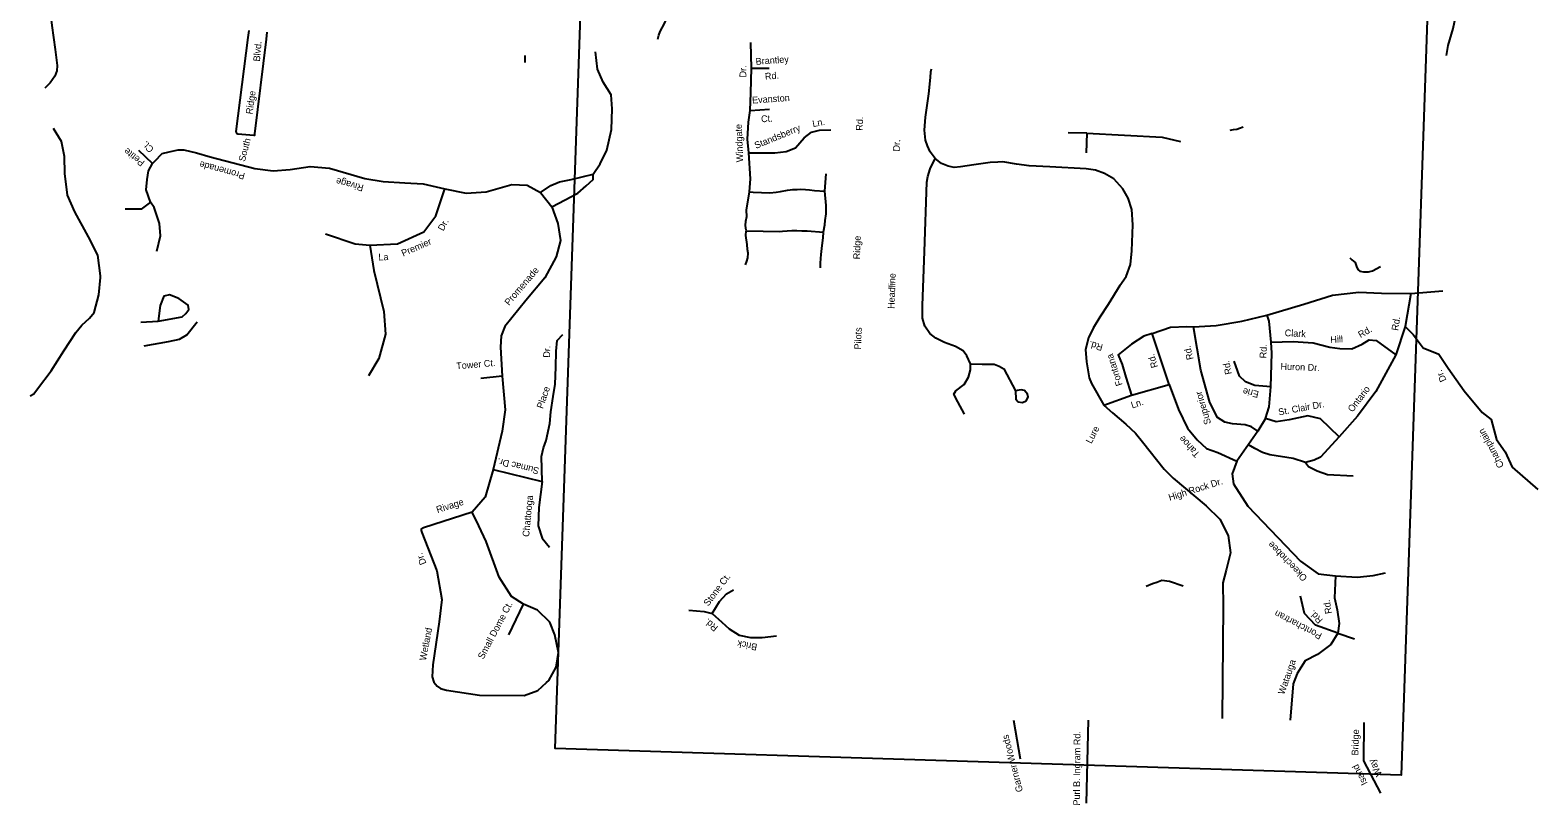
# Model space of a CAD drawing. Extents: x 2308163 to 2335412, y -96774 to 127732.
# Drawn here: x 2308692 to 2323317, y -96363 to -88852 of the extents above; entities that cross this region are included whole.
import ezdxf

# ---------------------------------------------------------------- set-up
doc = ezdxf.new("R2010")
doc.units = 0
for name, color, linetype in [('Old_Level_10', 7, 'Continuous'), ('Old_Level_35', 7, 'Continuous'), ('Old_Level_63', 7, 'Continuous')]:
    doc.layers.add(name, color=color, linetype=linetype)

msp = doc.modelspace()

# ---------------------------------------------------------------- linework, layer by layer
at = {"layer": 'Old_Level_35'}
for p, q in [((2310807, -88923), (2310816, -88856)), ((2310989, -88873), (2310981, -88940)), ((2313495, -89165), (2313493, -89097)), ((2316402, -90412), (2316415, -90245))]:
    msp.add_line(p, q, dxfattribs=at)
for points in [[(2314782, -88941), (2314789, -88901), (2314802, -88866), (2314844, -88788), (2314897, -88666), (2314973, -88472), (2315044, -88272), (2315156, -88000)], [(2308871, -88558), (2308875, -88590), (2308902, -88806), (2308935, -89040), (2308954, -89195), (2308952, -89248), (2308933, -89297), (2308885, -89364), (2308835, -89414)], [(2322432, -89098), (2322447, -89000), (2322494, -88836), (2322521, -88712), (2322527, -88652)], [(2310981, -88940), (2310869, -89858), (2310869, -89867), (2310868, -89870), (2310867, -89872), (2310864, -89873), (2310861, -89874), (2310705, -89860), (2310699, -89857), (2310696, -89852), (2310694, -89846), (2310693, -89841), (2310692, -89834), (2310807, -88923)], [(2313751, -90565), (2314005, -90432), (2314085, -90363), (2314152, -90301), (2314154, -90249), (2314222, -90148), (2314285, -90015), (2314330, -89816), (2314337, -89616), (2314329, -89480), (2314249, -89355), (2314195, -89230), (2314177, -89063)], [(2315671, -90421), (2315680, -90293), (2315663, -90041), (2315651, -89908), (2315660, -89743), (2315677, -89631), (2315683, -89460), (2315688, -89221), (2315682, -88971)], [(2315688, -89221), (2315862, -89221)], [(2317470, -90097), (2317422, -90031), (2317395, -89973), (2317377, -89918), (2317367, -89823), (2317378, -89695), (2317410, -89470), (2317426, -89311), (2317430, -89257), (2317434, -89228)], [(2315677, -89631), (2315865, -89618)], [(2320333, -89822), (2320366, -89816), (2320397, -89811), (2320424, -89802), (2320458, -89789)], [(2309375, -91234), (2309347, -91035), (2309258, -90857), (2309124, -90615), (2309054, -90452), (2309028, -90242), (2309024, -90076), (2308996, -89933), (2308920, -89807)], [(2315663, -90041), (2315916, -90043), (2316027, -90028), (2316117, -89993), (2316201, -89896), (2316270, -89841), (2316350, -89821), (2316459, -89819)], [(2318942, -89852), (2318761, -89848)], [(2318942, -89852), (2318934, -90042)], [(2318942, -89852), (2319674, -89890), (2319851, -89933)], [(2309880, -90145), (2309747, -90018)], [(2309858, -90519), (2309819, -90399), (2309828, -90300), (2309840, -90215), (2309880, -90145), (2309900, -90122), (2309974, -90049), (2310041, -90033), (2310127, -90012), (2310184, -90014), (2310306, -90042), (2310438, -90079)], [(2310438, -90079), (2310872, -90194), (2311049, -90216), (2311215, -90202), (2311409, -90173), (2311597, -90191), (2311937, -90289), (2312116, -90319), (2312328, -90331), (2312505, -90341), (2312716, -90391), (2312920, -90434), (2313117, -90421), (2313364, -90350), (2313513, -90356), (2313641, -90427), (2313751, -90565), (2313812, -90728), (2313838, -90890), (2313793, -91050), (2313683, -91255), (2313499, -91473), (2313297, -91726), (2313262, -91816), (2313254, -91926), (2313272, -92206), (2313300, -92534), (2313270, -92741), (2313182, -93112), (2313106, -93381), (2312979, -93526), (2312509, -93676), (2312484, -93690), (2312484, -93702), (2312491, -93722), (2312636, -94093), (2312686, -94371), (2312658, -94590), (2312597, -95005), (2312593, -95123), (2312607, -95175), (2312641, -95212), (2312671, -95236), (2312730, -95250), (2313051, -95301), (2313485, -95304), (2313616, -95253), (2313702, -95177), (2313722, -95158), (2313794, -95027), (2313818, -94886), (2313781, -94716), (2313734, -94592), (2313612, -94474), (2313476, -94418), (2313360, -94343), (2313241, -94154), (2313115, -93811), (2313045, -93659), (2312979, -93526)], [(2317812, -92086), (2317778, -92008), (2317743, -91961), (2317667, -91919), (2317560, -91879), (2317476, -91838), (2317418, -91793), (2317369, -91723), (2317347, -91646), (2317348, -91522), (2317368, -90997), (2317391, -90327), (2317400, -90272), (2317421, -90196), (2317470, -90097)], [(2319262, -91329), (2319323, -91241), (2319365, -91124), (2319377, -90992), (2319388, -90741), (2319378, -90590), (2319344, -90481), (2319292, -90391), (2319203, -90295), (2319112, -90242), (2319025, -90211), (2318937, -90196), (2318584, -90176), (2318381, -90167), (2318261, -90150), (2318128, -90130), (2318080, -90131), (2318004, -90136), (2317845, -90157), (2317716, -90178), (2317654, -90184), (2317597, -90171), (2317533, -90146), (2317470, -90097)], [(2313641, -90427), (2313743, -90358), (2313828, -90322), (2313939, -90300), (2314154, -90249)], [(2309922, -90995), (2309956, -90845), (2309946, -90726), (2309894, -90573), (2309858, -90519), (2309770, -90587), (2309614, -90587)], [(2311557, -90828), (2311845, -90925), (2311987, -90938), (2312255, -90923), (2312511, -90806), (2312627, -90653), (2312716, -90391)], [(2315636, -90792), (2315632, -90747), (2315634, -90703), (2315643, -90658), (2315642, -90597), (2315671, -90421)], [(2315671, -90421), (2315704, -90422), (2315785, -90427), (2315867, -90429), (2315927, -90424), (2315972, -90417), (2316038, -90405), (2316091, -90398), (2316132, -90398), (2316165, -90394), (2316214, -90397), (2316251, -90400), (2316300, -90407), (2316402, -90412)], [(2316386, -90808), (2316402, -90739), (2316404, -90698), (2316415, -90633), (2316412, -90552), (2316402, -90412)], [(2315630, -91128), (2315644, -91091), (2315653, -91060), (2315658, -91013), (2315650, -90978), (2315647, -90929), (2315635, -90844), (2315639, -90798)], [(2315642, -90797), (2315965, -90803), (2315989, -90801), (2316082, -90794), (2316129, -90795), (2316178, -90798), (2316228, -90798), (2316386, -90810)], [(2316357, -91157), (2316359, -91111), (2316361, -91066), (2316364, -91028), (2316372, -90970), (2316385, -90862), (2316389, -90813)], [(2311987, -90938), (2312026, -91183), (2312122, -91580), (2312138, -91801), (2312075, -92035), (2311975, -92205)], [(2321494, -91061), (2321514, -91078), (2321544, -91106), (2321558, -91143), (2321570, -91171), (2321590, -91188), (2321627, -91196), (2321673, -91196), (2321713, -91184), (2321789, -91142)], [(2308692, -92397), (2308728, -92377), (2308764, -92329), (2308895, -92154), (2309018, -91960), (2309135, -91783), (2309193, -91713), (2309268, -91643), (2309312, -91589), (2309359, -91419), (2309374, -91251), (2309375, -91234)], [(2319262, -91329), (2319148, -91513), (2319069, -91634), (2319005, -91742), (2318958, -91836), (2318930, -91948), (2318938, -92068), (2318965, -92222), (2318987, -92279), (2319107, -92489), (2319190, -92563), (2319319, -92672), (2319413, -92760), (2319482, -92842), (2319691, -93107), (2319778, -93196), (2320100, -93463), (2320232, -93593), (2320312, -93751), (2320336, -93918), (2320295, -94087), (2320261, -94211), (2320263, -94437), (2320254, -95525)], [(2319575, -91793), (2319753, -91733), (2319913, -91724), (2319976, -91728), (2320195, -91716), (2320446, -91675), (2320687, -91616), (2321048, -91509), (2321326, -91420), (2321581, -91393), (2321799, -91401), (2322085, -91404)], [(2322085, -91404), (2322030, -91724), (2321939, -92001), (2321745, -92357), (2321569, -92594), (2321388, -92795), (2321208, -92991), (2321148, -93022), (2321063, -93044), (2320943, -93005), (2320718, -92970), (2320646, -92948), (2320573, -92909), (2320509, -92872)], [(2322085, -91404), (2322394, -91381)], [(2309765, -91683), (2309934, -91674), (2310166, -91630), (2310202, -91600), (2310231, -91561), (2310226, -91520), (2310133, -91455), (2310044, -91417), (2309990, -91432), (2309953, -91521)], [(2309953, -91521), (2309934, -91674)], [(2309798, -91913), (2310035, -91872), (2310142, -91848), (2310212, -91805), (2310313, -91680)], [(2320731, -91878), (2320710, -91672), (2320692, -91615)], [(2313660, -93228), (2313653, -92986), (2313672, -92900), (2313696, -92831), (2313734, -92666), (2313743, -92553), (2313764, -92403), (2313784, -92285), (2313790, -92119), (2313796, -91963), (2313804, -91861), (2313860, -91803)], [(2319742, -92287), (2319575, -91793), (2319494, -91819), (2319374, -91895), (2319247, -91999), (2319284, -92093), (2319320, -92215), (2319374, -92392)], [(2320602, -92741), (2320538, -92697), (2320478, -92677), (2320354, -92669), (2320280, -92653), (2320208, -92609), (2320134, -92461), (2320049, -92150), (2319976, -91728)], [(2322030, -91724), (2322107, -91803), (2322205, -91931), (2322357, -91995), (2322448, -92130), (2322601, -92348), (2322778, -92559), (2322863, -92628), (2322915, -92821), (2322999, -92941), (2323067, -93090), (2323317, -93304)], [(2321388, -92795), (2321207, -92620), (2321087, -92592), (2320903, -92629), (2320780, -92649), (2320676, -92618), (2320709, -92505), (2320726, -92311), (2320738, -91983), (2320731, -91878)], [(2320731, -91878), (2320943, -91871), (2321136, -91882), (2321299, -91927), (2321396, -91939), (2321511, -91941), (2321613, -91896), (2321679, -91855), (2321749, -91860), (2321939, -92001)], [(2317755, -92574), (2317691, -92455), (2317653, -92382), (2317670, -92350), (2317753, -92289), (2317795, -92218), (2317814, -92146), (2317812, -92086)], [(2317812, -92086), (2317928, -92089), (2318042, -92092), (2318093, -92109), (2318136, -92136), (2318249, -92349), (2318253, -92430), (2318275, -92455), (2318317, -92463), (2318352, -92445), (2318374, -92411), (2318366, -92380), (2318336, -92346), (2318305, -92339), (2318265, -92345), (2318249, -92349)], [(2320726, -92311), (2320572, -92298), (2320481, -92261), (2320424, -92206), (2320372, -92062)], [(2313065, -92225), (2313272, -92203)], [(2319107, -92489), (2319374, -92392)], [(2319374, -92392), (2319742, -92287)], [(2319742, -92287), (2319831, -92531), (2319920, -92710), (2320011, -92823), (2320104, -92907), (2320213, -92948), (2320396, -93032)], [(2320676, -92618), (2320602, -92741), (2320396, -93032), (2320352, -93155), (2320364, -93250), (2320503, -93468), (2321013, -93999), (2321185, -94122), (2321353, -94142), (2321565, -94157), (2321719, -94140), (2321838, -94115)], [(2313182, -93112), (2313660, -93228), (2313625, -93480), (2313619, -93657), (2313658, -93777), (2313730, -93865)], [(2321063, -93044), (2321092, -93081), (2321175, -93124), (2321278, -93161), (2321525, -93173)], [(2321353, -94142), (2321345, -94355), (2321371, -94473), (2321388, -94605), (2321377, -94700), (2321308, -94808), (2321179, -94906), (2321060, -94968), (2320982, -95090), (2320942, -95191), (2320915, -95543)], [(2315307, -94507), (2315378, -94391), (2315448, -94316), (2315516, -94278)], [(2319516, -94243), (2319580, -94216), (2319621, -94203), (2319669, -94186), (2319744, -94195), (2319876, -94241)], [(2313335, -94713), (2313476, -94418)], [(2315082, -94474), (2315231, -94489), (2315307, -94507), (2315402, -94593), (2315472, -94657), (2315568, -94717), (2315680, -94741), (2315794, -94740), (2315932, -94723)], [(2321377, -94700), (2321160, -94622), (2321054, -94509), (2321016, -94339)], [(2321377, -94700), (2321537, -94753)], [(2318299, -95920), (2318233, -95545)], [(2318938, -96345), (2318957, -95541)], [(2321793, -96250), (2321628, -95936), (2321633, -95566)]]:
    msp.add_lwpolyline(points, dxfattribs=at)
at = {"layer": 'Old_Level_63'}
msp.add_lwpolyline([(2322444, -82932), (2321991, -96076), (2313786, -95817), (2314315, -80480)], dxfattribs=at)

# ---------------------------------------------------------------- texts
at = {"layer": 'Old_Level_10'}
for s, height, rotation, p in [('Blvd.', 65.6, 85.2272, (2310921, -89158)), ('Dr.', 65.6, 89.4385, (2315638, -89311)), ('Brantley', 65.6, 4.3646, (2315732, -89189)), ('Rd.', 65.6, 4.3646, (2315822, -89333)), ('Ridge', 65.6, 81.8623, (2310848, -89671)), ('Evanston', 65.6, 3.9715, (2315697, -89564)), ('Windgate', 65.6, 92.2238, (2315609, -90131)), ('Standsberry', 65.62, 22.4236, (2315734, -90004)), ('Ct.', 65.6, 3.9715, (2315784, -89746)), ('Ln.', 65.6, 10.8306, (2316286, -89792)), ('Rd.', 65.6, 87.9298, (2316767, -89828)), ('Ct.', 65.6, 134.3578, (2309897, -90002)), ('South ', 65.6, 75.4775, (2310775, -90131)), ('Dr.', 65.6, 87.0673, (2317126, -90030)), ('Petite', 65.6, 141.9823, (2309809, -90127)), ('Promenade', 65.6, 164.8185, (2310781, -90239)), ('Rivage ', 65.6, 164.9249, (2311932, -90354)), ('Dr.', 65.6, 61.5716, (2312700, -90805)), ('Premier ', 65.6, 23.573, (2312310, -91048)), ('Ridge', 65.6, 88.0247, (2316741, -91075)), ('La ', 65.6, 2.8628, (2312072, -91086)), ('Promenade', 65.6, 49.5056, (2313337, -91527)), ('Headline', 65.6, 88.0247, (2317076, -91555)), ('Rd.', 65.6, 80.9562, (2321961, -91769)), ('Pilots', 65.6, 87.8633, (2316751, -91949)), ('Clark', 65.6, 356.6269, (2320860, -91818)), ('Hill', 65.6, 3.1309, (2321306, -91885)), ('Rd.', 65.6, 29.8603, (2321597, -91839)), ('Dr.', 65.6, 87.4369, (2313733, -92029)), ('Rd.', 65.6, 164.5659, (2319103, -91900)), ('Fontana', 65.6, 107.7984, (2319290, -92290)), ('Rd.', 65.6, 103.6352, (2319977, -92040)), ('Rd.', 65.6, 87.8778, (2320683, -92035)), ('Tower Ct.', 65.6, 4.9538, (2312828, -92141)), ('Rd.', 65.6, 106.6838, (2319633, -92116)), ('Rd.', 65.6, 101.3226, (2320349, -92184)), ('Huron Dr.', 65.6, 358.0247, (2320820, -92144)), ('Dr.', 65.6, 116.2723, (2322433, -92244)), ('Place', 65.6, 71.0915, (2313665, -92527)), ('Superior', 65.6, 106.4077, (2320148, -92665)), ('Erie', 65.6, 167.3506, (2320615, -92354)), ('Ontario', 65.6, 52.5914, (2321519, -92561)), ('Ln.', 65.6, 18.5093, (2319382, -92521)), ('St. Clair Dr.', 65.62, 10.3937, (2320806, -92588)), ('Lure', 65.6, 62.5274, (2318986, -92867)), ('Champlain', 65.6, 118.4032, (2322991, -93076)), ('Tahoe', 65.6, 132.3947, (2320044, -92960)), ('Sumac Dr.', 65.6, 166.5432, (2313634, -93096)), ('High Rock Dr.', 65.62, 17.5209, (2319746, -93416)), ('Rivage ', 65.6, 17.4763, (2312643, -93534)), ('Chattooga', 65.6, 84.5243, (2313532, -93767)), ('Okeechobee', 65.6, 134.2898, (2321085, -94158)), ('Dr.', 65.6, 112.2366, (2312537, -94021)), ('Stone Ct.', 65.6, 52.9539, (2315270, -94442)), ('Small Dome Ct.', 65.62, 62.207, (2313088, -94957)), ('Pontchartran', 65.62, 152.5317, (2321229, -94705)), ('Rd.', 65.6, 134.4566, (2321236, -94567)), ('Rd.', 65.6, 99.3895, (2321320, -94506)), ('Rd.', 65.6, 140.7679, (2315371, -94637)), ('Wetland', 65.6, 79.2672, (2312532, -94968)), ('Brick', 65.6, 169.0975, (2315749, -94804)), ('Watauga', 65.6, 70.8529, (2320856, -95299)), ('Bridge', 65.6, 88.4171, (2321575, -95885)), ('Garner Woods', 65.62, 104.4911, (2318323, -96230)), ('Purl B. Ingram Rd.', 65.62, 89.5734, (2318875, -96370)), ('Way', 65.6, 117.301, (2321808, -96067)), ('Isand', 65.6, 117.301, (2321668, -96153))]:
    msp.add_text(s, height=height, rotation=rotation, dxfattribs=at).set_placement(p)

doc.saveas('drawing.dxf')
